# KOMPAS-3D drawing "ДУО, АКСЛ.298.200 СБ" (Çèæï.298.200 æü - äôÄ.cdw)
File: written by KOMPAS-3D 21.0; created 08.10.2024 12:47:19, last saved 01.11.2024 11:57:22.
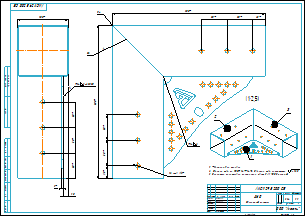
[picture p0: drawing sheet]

Sheet 1: A2, landscape

Document properties: Полное имя файла: C:\Users\Алексей Бочаров\YandexDisk\Соединения бруса\Соединения бруса\ДУО\АКСЛ.298.200 СБ - ДУО.cdw; Автор: Алексей Бочаров; Масса: 3.338231

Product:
- Part/product: ДУО  | designation АКСЛ.298.200 СБ
    Масса: 3.338231
    Форматы листов документа: A4
    source file: АКСЛ.298.200 - ДУО.spw, ДУО спецификация.spw
  - Component [assembly]: Перемычка  | designation АКСЛ.298.201  | pos. 1  | Масса: 0.308618; source file: ..\Перемычка.stp
  - Component [detail]: Профиль L = 300 мм  | designation АКСЛ.298.302  | pos. 2  | Масса: 1.514806; Форматы листов документа: A2; source file: ..\ТРИО\АКСЛ.298.302 - Профиль L = 300 мм.cdw, ..\ТРИО\Профиль L = 300 мм (1).m3d
  - Component [detail]: Профиль L = 300 мм  | designation АКСЛ.298.302-01  | pos. 2  | Масса: 1.514806; source file: ..\ТРИО\АКСЛ.298.302-01 - Профиль L = 300 мм.cdw, ..\ТРИО\Профиль L = 300 мм (2).m3d

Title block, sheet 1: Наименование: ДУО / Сборочный чертеж; designation: АКСЛ.298.200 СБ; Масса: 3,34; Количество листов документа: 1; organisation: ООО "Аксель"; Форматы листов документа: A2; stored path: C:\Users\Алексей Бочаров\Desktop\Соединения бруса\ДУО\ДУО Сборочный чертеж.cdw; Разработал: Бочаров; Проверил: Захаров; Утвердил: Гелетей

Views: Проекционный вид 2
Referenced files in C:\Users\Алексей Бочаров\Desktop\Соединения бруса\ДУО\: ДУО сборка.a3d
Referenced files in C:\Users\Алексей Бочаров\YandexDisk\Соединения бруса\Соединения бруса\ДУО\: Профиль L = 300 мм.m3d, Профиль L = 300 мм зеркальный.m3d, АКСЛ.298.202 - Профиль L = 300 мм.cdw
Referenced files in C:\Users\Алексей Бочаров\YandexDisk\Соединения бруса\Соединения бруса\: Перемычка.stp
Referenced files in C:\Users\Алексей Бочаров\YandexDisk\Соединения бруса\Соединения бруса\ТРИО\: Профиль L = 300 мм (2).m3d, АКСЛ.298.302-01 - Профиль L = 300 мм.cdw, Профиль L = 300 мм (1).m3d, АКСЛ.298.302 - Профиль L = 300 мм.cdw
Referenced files in C:\Users\79253\YandexDisk\Соединения бруса\Соединения бруса\ТРИО\: Профиль L = 300 мм (1).m3d, Профиль L = 300 мм (2).m3d
Referenced files in C:\Users\79253\YandexDisk\Соединения бруса\Соединения бруса\ДУО\: ДУО сборка.a3d
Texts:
  АКСЛ.298.202
  Профиль L = 300 мм
  АКСЛ.298.202 - 01
  АКСЛ.298.202 - 01
  АКСЛ.298.202-01
  АКСЛ.298.201
  Перемычка
  АКСЛ.298.302 - 01
  АКСЛ.298.302 - 01
  АКСЛ.298.302-01
  АКСЛ.298.302
  АКСЛ.298.200
  АКСЛ.298.201 Перемычка
  АКСЛ.298.302 Профиль L = 300 мм
  АКСЛ.298.302-01 Профиль L = 300 мм
  АКСЛ.298.200 СБ ДУО
Dimensions and other numbers on the sheet: 2; 100; 3; 10; 50; 1; 1:1; 3,34; 3D Узел_3; 3D Узел_3 3D Узел_3; 3D Узел_2; 3D Узел_2 3D Узел_2; 0; 0 0; 01

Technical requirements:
  *Размеры для справок.
  Сварные швы по ГОСТ 14771-76. Сварные швы зачистить  Ra 12,5.
  Покрытие порошковое полимерное, цвет RAl 9005 черный.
